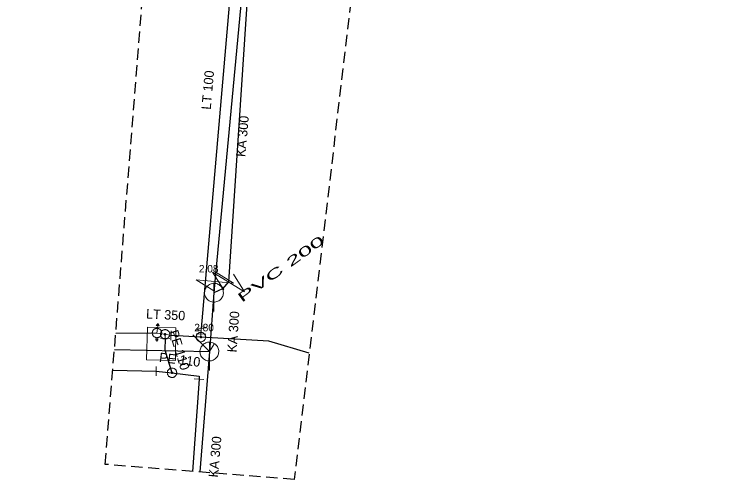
# Model space of a CAD drawing. Extents: x -686636 to -686482, y -972667 to -972167.
# Drawn here: x -686559.3 to -686482.1, y -972667.3 to -972617.8 of the extents above; entities that cross this region are included whole.
import ezdxf

# ---------------------------------------------------------------- set-up
doc = ezdxf.new("R2010")
doc.units = 0
doc.header["$LTSCALE"] = 0.4
doc.linetypes.add('MEDIUM_DASHED', pattern=[4.5, 3, -1.5])
for name, color, linetype, lineweight in [('1', 7, 'MEDIUM_DASHED', 25), ('11', 7, 'Continuous', 13), ('14', 7, 'Continuous', 25), ('17', 7, 'Continuous', 25), ('2', 7, 'Continuous', 13), ('22', 7, 'Continuous', 13), ('23', 7, 'Continuous', 13), ('31', 7, 'Continuous', 13), ('34', 7, 'Continuous', 13), ('47', 7, 'Continuous', 13)]:
    doc.layers.add(name, color=color, linetype=linetype, lineweight=lineweight)

msp = doc.modelspace()

# ---------------------------------------------------------------- linework, layer by layer
at = {"layer": '1'}
msp.add_lwpolyline([(-686523.086, -972200.227), (-686492.539, -972167.269), (-686482.089, -972185.758), (-686542.379, -972270.164), (-686548.006, -972279.81), (-686543.183, -972295.084), (-686523.086, -972321.612), (-686521.478, -972360.197), (-686540.771, -972442.192), (-686521.478, -972473.543), (-686515.047, -972510.521), (-686519.067, -972578.85), (-686529.517, -972667.276), (-686549.614, -972665.668), (-686542.379, -972574.831), (-686589.003, -972562.773), (-686636.432, -972544.284), (-686625.981, -972525.795), (-686541.575, -972549.911), (-686539.967, -972501.678), (-686569.711, -972440.584), (-686549.614, -972329.65), (-686564.887, -972297.496), (-686572.926, -972277.399)], close=True, dxfattribs=at)
at = {"layer": '11'}
for p in [(-686540.289, -972651.87), (-686538, -972652.82)]:
    msp.add_line(p, (-686538.55, -972653.66), dxfattribs=at)
at = {"layer": '14'}
for p, q in [((-686534.882, -972613.416), (-686537.964, -972646.203)), ((-686537.964, -972646.203), (-686538.059, -972647.399)), ((-686538.059, -972647.399), (-686538.55, -972653.66)), ((-686548.64, -972653.436), (-686538.55, -972653.66)), ((-686538.55, -972653.66), (-686539.578, -972666.471))]:
    msp.add_line(p, q, dxfattribs=at)
at = {"layer": '14', "lineweight": 13}
for p, q in [((-686543.26, -972651.829), (-686544.14, -972651.71)), ((-686543.26, -972651.829), (-686543.239, -972652.27)), ((-686542.62, -972651.94), (-686543.26, -972651.829)), ((-686539.45, -972652.117), (-686539.44, -972651.78)), ((-686539.44, -972651.78), (-686539.43, -972651.21))]:
    msp.add_line(p, q, dxfattribs=at)
at = {"layer": '14'}
for points in [[(-686529.998, -972548.457), (-686530.171, -972549.975), (-686536.5, -972646.26)], [(-686536.5, -972646.26), (-686537.149, -972646.989), (-686538.059, -972647.399)]]:
    msp.add_lwpolyline(points, dxfattribs=at)
at = {"layer": '17'}
for p, q in [((-686534.899, -972598.886), (-686539.43, -972651.21)), ((-686544.14, -972651.71), (-686548.504, -972651.735)), ((-686548.816, -972655.651), (-686544.21, -972655.739)), ((-686544.21, -972655.739), (-686542.52, -972655.92)), ((-686539.649, -972656.6), (-686540.358, -972666.408))]:
    msp.add_line(p, q, dxfattribs=at)
for points in [[(-686543.239, -972652.27), (-686543.28, -972653.48), (-686542.52, -972655.92)], [(-686527.928, -972653.827), (-686532.219, -972652.55), (-686539.45, -972652.117), (-686542.62, -972651.94)], [(-686542.52, -972655.92), (-686539.62, -972656.27), (-686539.649, -972656.6)]]:
    msp.add_lwpolyline(points, dxfattribs=at)
at = {"layer": '2'}
msp.add_lwpolyline([(-686545.123, -972651.071), (-686542.107, -972651.153), (-686542.161, -972654.608), (-686545.232, -972654.553)], close=True, dxfattribs=at)
at = {"layer": '22'}
for p, q in [((-686538.059, -972649.399), (-686538.058, -972646.399)), ((-686538.55, -972655.66), (-686538.549, -972652.66))]:
    msp.add_line(p, q, dxfattribs=at)
for points in [[(-686537.059, -972647.399), (-686537.064, -972647.29), (-686537.082, -972647.182), (-686537.112, -972647.076), (-686537.152, -972646.975), (-686537.204, -972646.878), (-686537.266, -972646.788), (-686537.338, -972646.705), (-686537.418, -972646.631), (-686537.506, -972646.565), (-686537.6, -972646.51), (-686537.7, -972646.465), (-686537.805, -972646.432), (-686537.912, -972646.41), (-686538.021, -972646.4), (-686538.131, -972646.402), (-686538.239, -972646.416), (-686538.346, -972646.441), (-686538.449, -972646.478), (-686538.547, -972646.527), (-686538.639, -972646.585), (-686538.725, -972646.654), (-686538.802, -972646.731), (-686538.871, -972646.817), (-686538.93, -972646.909), (-686538.978, -972647.007), (-686539.015, -972647.11), (-686539.041, -972647.217), (-686539.055, -972647.325), (-686539.058, -972647.435), (-686539.048, -972647.544), (-686539.027, -972647.651), (-686538.993, -972647.755), (-686538.949, -972647.855), (-686538.894, -972647.95), (-686538.828, -972648.038), (-686538.754, -972648.118), (-686538.671, -972648.19), (-686538.581, -972648.252), (-686538.485, -972648.304), (-686538.383, -972648.345), (-686538.278, -972648.375), (-686538.17, -972648.393), (-686538.06, -972648.399), (-686537.951, -972648.393), (-686537.843, -972648.375), (-686537.738, -972648.346), (-686537.636, -972648.305), (-686537.539, -972648.253), (-686537.449, -972648.191), (-686537.366, -972648.12), (-686537.291, -972648.04), (-686537.226, -972647.952), (-686537.17, -972647.858), (-686537.126, -972647.758), (-686537.092, -972647.654), (-686537.07, -972647.546), (-686537.06, -972647.437)], [(-686537.55, -972653.66), (-686537.555, -972653.551), (-686537.573, -972653.443), (-686537.603, -972653.337), (-686537.643, -972653.236), (-686537.695, -972653.139), (-686537.757, -972653.049), (-686537.829, -972652.966), (-686537.909, -972652.892), (-686537.997, -972652.826), (-686538.091, -972652.771), (-686538.191, -972652.726), (-686538.296, -972652.693), (-686538.403, -972652.671), (-686538.512, -972652.661), (-686538.622, -972652.663), (-686538.73, -972652.677), (-686538.837, -972652.702), (-686538.94, -972652.739), (-686539.038, -972652.788), (-686539.13, -972652.846), (-686539.216, -972652.915), (-686539.293, -972652.992), (-686539.362, -972653.078), (-686539.421, -972653.17), (-686539.469, -972653.268), (-686539.506, -972653.371), (-686539.532, -972653.478), (-686539.546, -972653.586), (-686539.549, -972653.696), (-686539.539, -972653.805), (-686539.518, -972653.912), (-686539.484, -972654.016), (-686539.44, -972654.116), (-686539.385, -972654.211), (-686539.319, -972654.299), (-686539.245, -972654.379), (-686539.162, -972654.451), (-686539.072, -972654.513), (-686538.976, -972654.565), (-686538.874, -972654.606), (-686538.769, -972654.636), (-686538.661, -972654.654), (-686538.551, -972654.66), (-686538.442, -972654.654), (-686538.334, -972654.636), (-686538.229, -972654.607), (-686538.127, -972654.566), (-686538.03, -972654.514), (-686537.94, -972654.452), (-686537.857, -972654.381), (-686537.782, -972654.301), (-686537.717, -972654.213), (-686537.661, -972654.119), (-686537.617, -972654.019), (-686537.583, -972653.915), (-686537.561, -972653.807), (-686537.551, -972653.698)]]:
    msp.add_lwpolyline(points, close=True, dxfattribs=at)
at = {"layer": '23'}
msp.add_line((-686544.222, -972652.357), (-686544.026, -972652.356), dxfattribs=at)
for points in [[(-686543.83, -972651.277), (-686543.873, -972651.249), (-686543.921, -972651.227), (-686543.969, -972651.208), (-686544.021, -972651.196), (-686544.073, -972651.19), (-686544.125, -972651.187), (-686544.177, -972651.191), (-686544.228, -972651.2), (-686544.279, -972651.214), (-686544.327, -972651.234), (-686544.374, -972651.258), (-686544.417, -972651.287), (-686544.457, -972651.322), (-686544.494, -972651.358), (-686544.525, -972651.399), (-686544.554, -972651.444), (-686544.577, -972651.492), (-686544.594, -972651.541), (-686544.606, -972651.592), (-686544.614, -972651.643), (-686544.617, -972651.695), (-686544.613, -972651.748), (-686544.604, -972651.8), (-686544.589, -972651.849), (-686544.569, -972651.898), (-686544.545, -972651.943), (-686544.515, -972651.987), (-686544.482, -972652.027), (-686544.444, -972652.063), (-686544.403, -972652.096), (-686544.359, -972652.123), (-686544.312, -972652.147), (-686544.262, -972652.165), (-686544.212, -972652.177), (-686544.161, -972652.184), (-686544.109, -972652.187), (-686544.055, -972652.183), (-686544.005, -972652.174), (-686543.953, -972652.159)], [(-686544.617, -972651.695), (-686544.613, -972651.748), (-686544.604, -972651.8), (-686544.589, -972651.849), (-686544.569, -972651.898), (-686544.545, -972651.943), (-686544.515, -972651.987), (-686544.482, -972652.027), (-686544.444, -972652.063), (-686544.403, -972652.096), (-686544.359, -972652.123), (-686544.312, -972652.147), (-686544.262, -972652.165), (-686544.212, -972652.177), (-686544.161, -972652.184), (-686544.109, -972652.187), (-686544.055, -972652.183), (-686544.005, -972652.174), (-686543.953, -972652.159), (-686543.906, -972652.141), (-686543.859, -972652.116), (-686543.815, -972652.085), (-686543.776, -972652.052), (-686543.739, -972652.014), (-686543.706, -972651.973), (-686543.679, -972651.929), (-686543.656, -972651.881), (-686543.639, -972651.833), (-686543.626, -972651.782), (-686543.619, -972651.73), (-686543.617, -972651.678), (-686543.62, -972651.626), (-686543.629, -972651.574), (-686543.644, -972651.523), (-686543.663, -972651.475), (-686543.688, -972651.43), (-686543.717, -972651.387), (-686543.751, -972651.346), (-686543.789, -972651.309), (-686543.83, -972651.277)], [(-686544.594, -972651.541), (-686544.606, -972651.592), (-686544.614, -972651.643), (-686544.617, -972651.695)], [(-686543.953, -972652.159), (-686543.906, -972652.141), (-686543.859, -972652.116), (-686543.815, -972652.085), (-686543.776, -972652.052), (-686543.739, -972652.014), (-686543.706, -972651.973), (-686543.679, -972651.929), (-686543.656, -972651.881), (-686543.639, -972651.833), (-686543.626, -972651.782), (-686543.619, -972651.73), (-686543.617, -972651.678), (-686543.62, -972651.626), (-686543.629, -972651.574), (-686543.644, -972651.523), (-686543.663, -972651.475), (-686543.688, -972651.43), (-686543.717, -972651.387), (-686543.751, -972651.346), (-686543.789, -972651.309), (-686543.83, -972651.277), (-686543.873, -972651.249), (-686543.921, -972651.227), (-686543.969, -972651.208), (-686544.021, -972651.196), (-686544.073, -972651.19), (-686544.125, -972651.187), (-686544.177, -972651.191), (-686544.228, -972651.2), (-686544.279, -972651.214), (-686544.327, -972651.234), (-686544.374, -972651.258), (-686544.417, -972651.287), (-686544.457, -972651.322), (-686544.494, -972651.358), (-686544.525, -972651.399), (-686544.554, -972651.444), (-686544.577, -972651.492), (-686544.594, -972651.541)], [(-686544.026, -972652.259), (-686544.025, -972652.408), (-686544.124, -972652.56), (-686544.221, -972652.409), (-686544.222, -972652.26)]]:
    msp.add_lwpolyline(points, dxfattribs=at)
at = {"layer": '31'}
for points in [[(-686537.87, -972645.207), (-686535.973, -972646.39), (-686539.955, -972646.015), (-686538.058, -972647.198)], [(-686537.027, -972647.109), (-686538.198, -972645.204), (-686534.8, -972647.315), (-686535.971, -972645.41)]]:
    msp.add_lwpolyline(points, dxfattribs=at)
at = {"layer": '34'}
for p, q in [((-686544.172, -972650.869), (-686543.883, -972650.904)), ((-686544.148, -972650.842), (-686543.899, -972650.872)), ((-686544.139, -972651.709), (-686544.031, -972650.916)), ((-686544.124, -972650.814), (-686543.915, -972650.84)), ((-686544.1, -972650.787), (-686543.932, -972650.808)), ((-686544.078, -972650.76), (-686543.948, -972650.775)), ((-686544.054, -972650.733), (-686543.963, -972650.743)), ((-686544.03, -972650.705), (-686543.979, -972650.712)), ((-686544.006, -972650.678), (-686543.996, -972650.679)), ((-686542.647, -972652.439), (-686542.591, -972651.44)), ((-686539.939, -972651.765), (-686538.94, -972651.795)), ((-686542.739, -972652.286), (-686543.738, -972652.252)), ((-686544.2, -972655.239), (-686544.22, -972656.238)), ((-686539.151, -972656.644), (-686540.146, -972656.554))]:
    msp.add_line(p, q, dxfattribs=at)
msp.add_lwpolyline([(-686543.867, -972650.937), (-686544, -972650.67), (-686544.195, -972650.896)], close=True, dxfattribs=at)
at = {"layer": '47'}
msp.add_line((-686538.923, -972651.155), (-686539.412, -972651.009), dxfattribs=at)
for points in [[(-686543.752, -972651.744), (-686543.758, -972651.796), (-686543.759, -972651.848), (-686543.754, -972651.9), (-686543.744, -972651.951), (-686543.729, -972652.002), (-686543.707, -972652.05), (-686543.682, -972652.095), (-686543.652, -972652.138), (-686543.618, -972652.177), (-686543.579, -972652.213), (-686543.537, -972652.245), (-686543.492, -972652.271), (-686543.445, -972652.293), (-686543.395, -972652.31), (-686543.344, -972652.321), (-686543.292, -972652.327), (-686543.24, -972652.328), (-686543.187, -972652.323), (-686543.137, -972652.313), (-686543.086, -972652.298), (-686543.038, -972652.276), (-686542.992, -972652.251), (-686542.949, -972652.221), (-686542.91, -972652.187), (-686542.875, -972652.148), (-686542.843, -972652.106), (-686542.816, -972652.061), (-686542.795, -972652.014), (-686542.778, -972651.964), (-686542.767, -972651.913), (-686542.761, -972651.861), (-686542.76, -972651.809), (-686542.764, -972651.756), (-686542.775, -972651.706), (-686542.79, -972651.655), (-686542.811, -972651.607), (-686542.836, -972651.561), (-686542.866, -972651.519), (-686542.901, -972651.479), (-686542.94, -972651.444), (-686542.982, -972651.412), (-686543.026, -972651.386), (-686543.074, -972651.364), (-686543.124, -972651.347), (-686543.175, -972651.336), (-686543.227, -972651.33), (-686543.279, -972651.329), (-686543.331, -972651.333), (-686543.382, -972651.344), (-686543.433, -972651.359), (-686543.481, -972651.38), (-686543.526, -972651.405), (-686543.568, -972651.435), (-686543.608, -972651.47), (-686543.644, -972651.509), (-686543.676, -972651.551), (-686543.701, -972651.595), (-686543.724, -972651.643), (-686543.741, -972651.693)], [(-686543.34, -972651.815), (-686543.342, -972651.823), (-686543.341, -972651.832), (-686543.341, -972651.84), (-686543.339, -972651.848), (-686543.336, -972651.857), (-686543.333, -972651.865), (-686543.329, -972651.872), (-686543.324, -972651.879), (-686543.318, -972651.885), (-686543.312, -972651.892), (-686543.305, -972651.897), (-686543.297, -972651.901), (-686543.29, -972651.904), (-686543.282, -972651.908), (-686543.273, -972651.909), (-686543.265, -972651.911), (-686543.256, -972651.91), (-686543.248, -972651.91), (-686543.24, -972651.908), (-686543.231, -972651.905), (-686543.223, -972651.902), (-686543.216, -972651.898), (-686543.209, -972651.893), (-686543.202, -972651.887), (-686543.196, -972651.881), (-686543.191, -972651.874), (-686543.187, -972651.866), (-686543.184, -972651.859), (-686543.18, -972651.851), (-686543.179, -972651.842), (-686543.177, -972651.834), (-686543.178, -972651.825), (-686543.178, -972651.817), (-686543.18, -972651.809), (-686543.183, -972651.8), (-686543.185, -972651.793), (-686543.19, -972651.785), (-686543.195, -972651.778), (-686543.201, -972651.771), (-686543.207, -972651.765), (-686543.214, -972651.76), (-686543.222, -972651.756), (-686543.229, -972651.753), (-686543.237, -972651.749), (-686543.246, -972651.748), (-686543.254, -972651.746), (-686543.263, -972651.747), (-686543.271, -972651.747), (-686543.279, -972651.749), (-686543.288, -972651.752), (-686543.295, -972651.754), (-686543.303, -972651.759), (-686543.31, -972651.764), (-686543.316, -972651.77), (-686543.323, -972651.776), (-686543.328, -972651.783), (-686543.332, -972651.791), (-686543.335, -972651.798), (-686543.339, -972651.806)], [(-686539.949, -972652.089), (-686539.949, -972652.141), (-686539.944, -972652.193), (-686539.932, -972652.244), (-686539.917, -972652.294), (-686539.896, -972652.342), (-686539.869, -972652.387), (-686539.839, -972652.429), (-686539.804, -972652.468), (-686539.766, -972652.503), (-686539.723, -972652.535), (-686539.678, -972652.561), (-686539.63, -972652.582), (-686539.581, -972652.599), (-686539.529, -972652.61), (-686539.477, -972652.616), (-686539.425, -972652.616), (-686539.373, -972652.611), (-686539.321, -972652.599), (-686539.272, -972652.584), (-686539.224, -972652.563), (-686539.179, -972652.536), (-686539.136, -972652.506), (-686539.097, -972652.471), (-686539.062, -972652.433), (-686539.031, -972652.39), (-686539.005, -972652.345), (-686538.983, -972652.297), (-686538.967, -972652.248), (-686538.956, -972652.196), (-686538.95, -972652.144), (-686538.95, -972652.092), (-686538.955, -972652.04), (-686538.966, -972651.988), (-686538.982, -972651.939), (-686539.003, -972651.891), (-686539.029, -972651.846), (-686539.059, -972651.803), (-686539.094, -972651.764), (-686539.133, -972651.729), (-686539.176, -972651.698), (-686539.221, -972651.672), (-686539.268, -972651.65), (-686539.318, -972651.634), (-686539.37, -972651.623), (-686539.422, -972651.617), (-686539.474, -972651.617), (-686539.526, -972651.622), (-686539.577, -972651.633), (-686539.627, -972651.649), (-686539.675, -972651.67), (-686539.72, -972651.696), (-686539.762, -972651.726), (-686539.801, -972651.761), (-686539.836, -972651.8), (-686539.868, -972651.843), (-686539.894, -972651.888), (-686539.915, -972651.935), (-686539.932, -972651.985), (-686539.943, -972652.037)], [(-686539.531, -972652.112), (-686539.532, -972652.121), (-686539.53, -972652.129), (-686539.529, -972652.137), (-686539.526, -972652.145), (-686539.523, -972652.153), (-686539.518, -972652.161), (-686539.513, -972652.168), (-686539.508, -972652.174), (-686539.501, -972652.18), (-686539.494, -972652.185), (-686539.487, -972652.19), (-686539.479, -972652.193), (-686539.471, -972652.195), (-686539.463, -972652.198), (-686539.454, -972652.198), (-686539.445, -972652.199), (-686539.437, -972652.197), (-686539.429, -972652.196), (-686539.421, -972652.193), (-686539.413, -972652.19), (-686539.405, -972652.185), (-686539.398, -972652.18), (-686539.392, -972652.175), (-686539.385, -972652.168), (-686539.381, -972652.161), (-686539.376, -972652.154), (-686539.373, -972652.146), (-686539.371, -972652.138), (-686539.368, -972652.13), (-686539.368, -972652.121), (-686539.367, -972652.112), (-686539.369, -972652.104), (-686539.37, -972652.096), (-686539.373, -972652.088), (-686539.376, -972652.08), (-686539.38, -972652.072), (-686539.386, -972652.065), (-686539.391, -972652.059), (-686539.398, -972652.052), (-686539.405, -972652.048), (-686539.412, -972652.043), (-686539.42, -972652.04), (-686539.428, -972652.038), (-686539.436, -972652.035), (-686539.445, -972652.035), (-686539.454, -972652.034), (-686539.462, -972652.036), (-686539.47, -972652.037), (-686539.478, -972652.04), (-686539.486, -972652.043), (-686539.494, -972652.047), (-686539.501, -972652.053), (-686539.507, -972652.058), (-686539.513, -972652.065), (-686539.518, -972652.072), (-686539.523, -972652.079), (-686539.526, -972652.087), (-686539.528, -972652.095), (-686539.531, -972652.103)], [(-686543.018, -972655.883), (-686543.019, -972655.935), (-686543.015, -972655.988), (-686543.004, -972656.038), (-686542.99, -972656.089), (-686542.97, -972656.137), (-686542.944, -972656.183), (-686542.914, -972656.226), (-686542.88, -972656.265), (-686542.842, -972656.301), (-686542.8, -972656.333), (-686542.755, -972656.36), (-686542.708, -972656.382), (-686542.659, -972656.4), (-686542.608, -972656.411), (-686542.556, -972656.418), (-686542.504, -972656.419), (-686542.451, -972656.415), (-686542.4, -972656.405), (-686542.35, -972656.39), (-686542.302, -972656.37), (-686542.256, -972656.344), (-686542.212, -972656.314), (-686542.173, -972656.28), (-686542.137, -972656.242), (-686542.106, -972656.2), (-686542.079, -972656.155), (-686542.056, -972656.108), (-686542.039, -972656.059), (-686542.028, -972656.008), (-686542.021, -972655.956), (-686542.02, -972655.904), (-686542.024, -972655.851), (-686542.033, -972655.8), (-686542.049, -972655.75), (-686542.069, -972655.702), (-686542.094, -972655.656), (-686542.124, -972655.613), (-686542.158, -972655.573), (-686542.197, -972655.537), (-686542.239, -972655.506), (-686542.284, -972655.479), (-686542.33, -972655.456), (-686542.38, -972655.439), (-686542.431, -972655.428), (-686542.483, -972655.421), (-686542.535, -972655.42), (-686542.588, -972655.424), (-686542.638, -972655.434), (-686542.689, -972655.449), (-686542.737, -972655.469), (-686542.783, -972655.494), (-686542.825, -972655.524), (-686542.865, -972655.558), (-686542.901, -972655.597), (-686542.933, -972655.639), (-686542.96, -972655.684), (-686542.982, -972655.73), (-686543, -972655.78), (-686543.011, -972655.831)], [(-686542.601, -972655.914), (-686542.602, -972655.922), (-686542.601, -972655.931), (-686542.599, -972655.939), (-686542.597, -972655.947), (-686542.593, -972655.955), (-686542.589, -972655.963), (-686542.584, -972655.97), (-686542.579, -972655.976), (-686542.572, -972655.982), (-686542.566, -972655.987), (-686542.558, -972655.992), (-686542.55, -972655.995), (-686542.542, -972655.998), (-686542.534, -972656.001), (-686542.525, -972656.001), (-686542.517, -972656.002), (-686542.508, -972656.001), (-686542.5, -972655.999), (-686542.492, -972655.997), (-686542.484, -972655.993), (-686542.476, -972655.989), (-686542.469, -972655.984), (-686542.463, -972655.979), (-686542.456, -972655.972), (-686542.452, -972655.966), (-686542.447, -972655.958), (-686542.444, -972655.95), (-686542.441, -972655.942), (-686542.438, -972655.934), (-686542.438, -972655.925), (-686542.437, -972655.917), (-686542.438, -972655.908), (-686542.44, -972655.9), (-686542.442, -972655.892), (-686542.446, -972655.884), (-686542.449, -972655.877), (-686542.455, -972655.869), (-686542.46, -972655.863), (-686542.467, -972655.856), (-686542.473, -972655.852), (-686542.481, -972655.847), (-686542.489, -972655.844), (-686542.497, -972655.841), (-686542.505, -972655.838), (-686542.514, -972655.838), (-686542.522, -972655.837), (-686542.531, -972655.838), (-686542.539, -972655.84), (-686542.547, -972655.842), (-686542.555, -972655.846), (-686542.562, -972655.849), (-686542.57, -972655.855), (-686542.576, -972655.86), (-686542.582, -972655.867), (-686542.587, -972655.873), (-686542.592, -972655.881), (-686542.595, -972655.889), (-686542.598, -972655.897), (-686542.601, -972655.905)]]:
    msp.add_lwpolyline(points, close=True, dxfattribs=at)
msp.add_lwpolyline([(-686538.923, -972651.155), (-686539.936, -972651.264), (-686539.447, -972651.41)], dxfattribs=at)

# ---------------------------------------------------------------- texts
at = {"layer": '1'}
for s, rotation, p in [('LT 100', 85, (-686538.404, -972627.951)), ('KA 300', 85, (-686534.726, -972632.982)), ('LT 350', 357, (-686545.298, -972650.135)), ('KA 300', 86, (-686535.659, -972653.78)), ('PE 110', 287, (-686542.85, -972651.542)), ('PE 110', 353, (-686543.93, -972654.756)), ('KA 300', 85, (-686537.635, -972667.091))]:
    msp.add_text(s, height=1, rotation=rotation, dxfattribs=at).set_placement(p)
at = {"layer": '1', "width": 2.05}
msp.add_text('PVC 200 ', height=1, rotation=36, dxfattribs=at).set_placement((-686535.107, -972648.493))
at = {"layer": '1'}
for s, p in [('2,08', (-686539.66, -972645.247)), ('2,80', (-686540.15, -972651.507))]:
    msp.add_text(s, height=0.8, dxfattribs=at).set_placement(p)

doc.saveas('drawing.dxf')
